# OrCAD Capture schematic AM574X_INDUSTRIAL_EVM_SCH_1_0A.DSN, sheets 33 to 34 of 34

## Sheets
33 Pg04: Processor Pwr Decoupling: size C
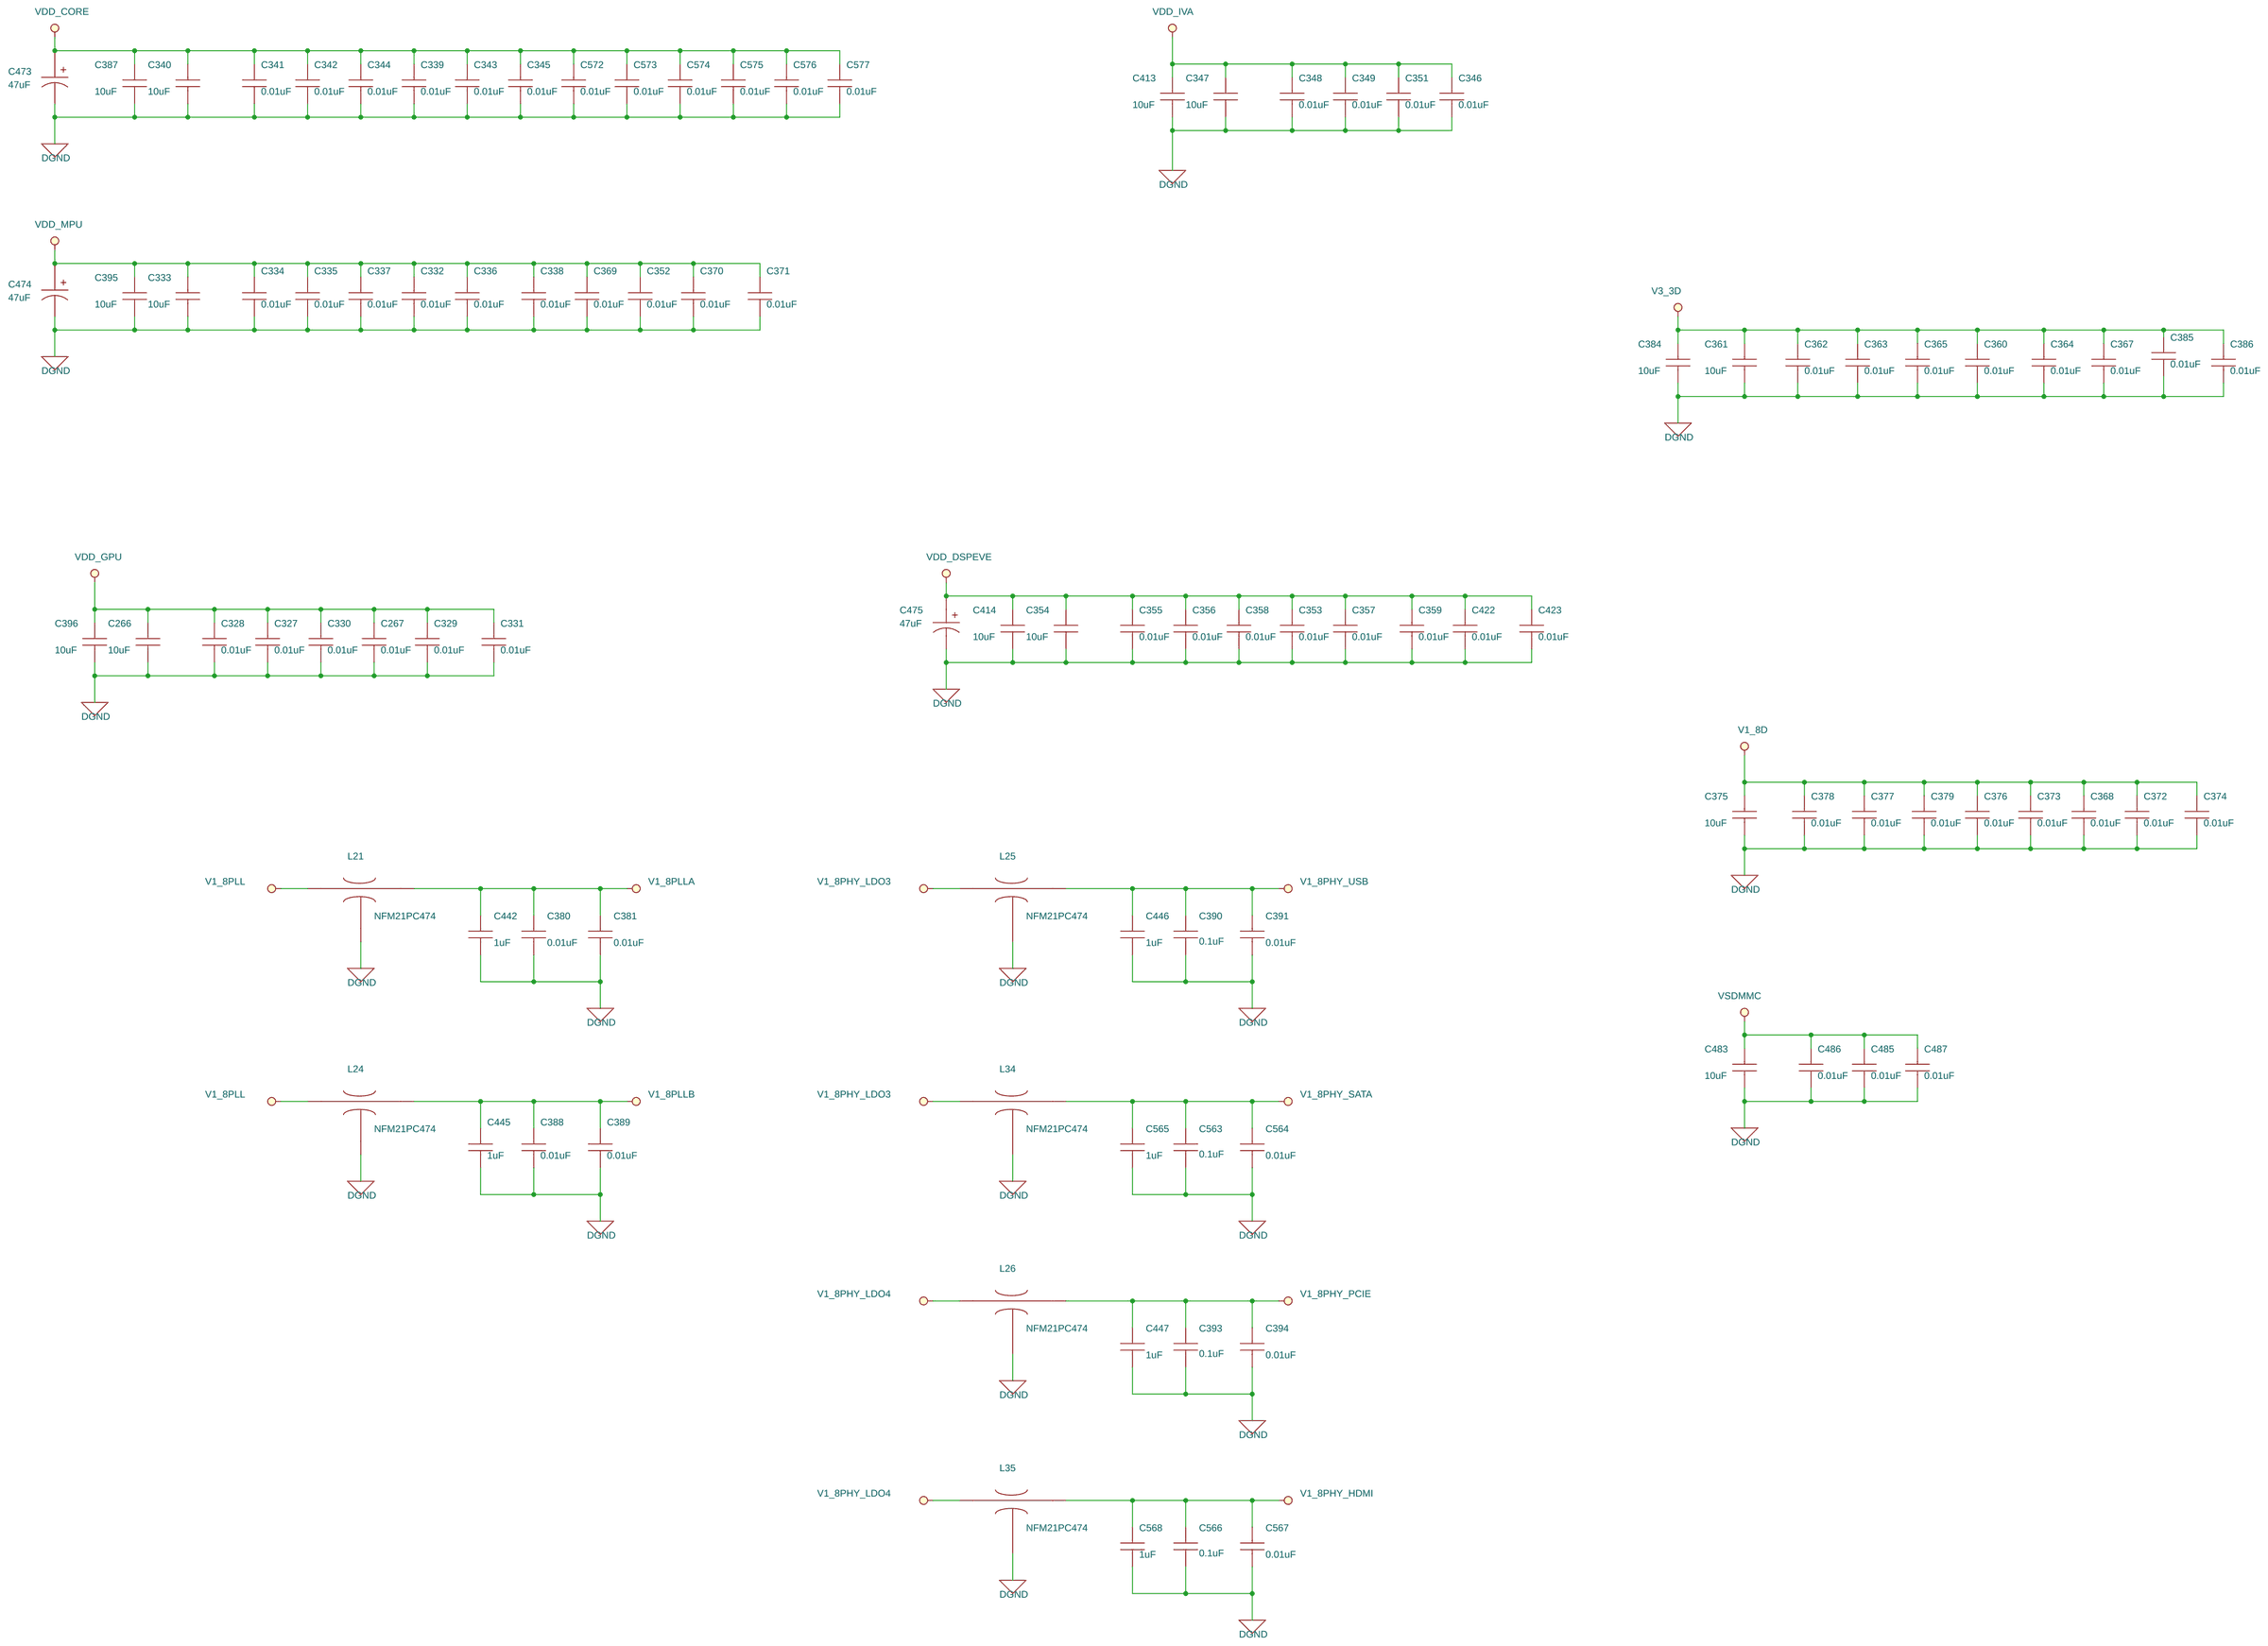
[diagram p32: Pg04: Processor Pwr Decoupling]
34 Pg15: Ind Ethrnt & Status LED's: size C
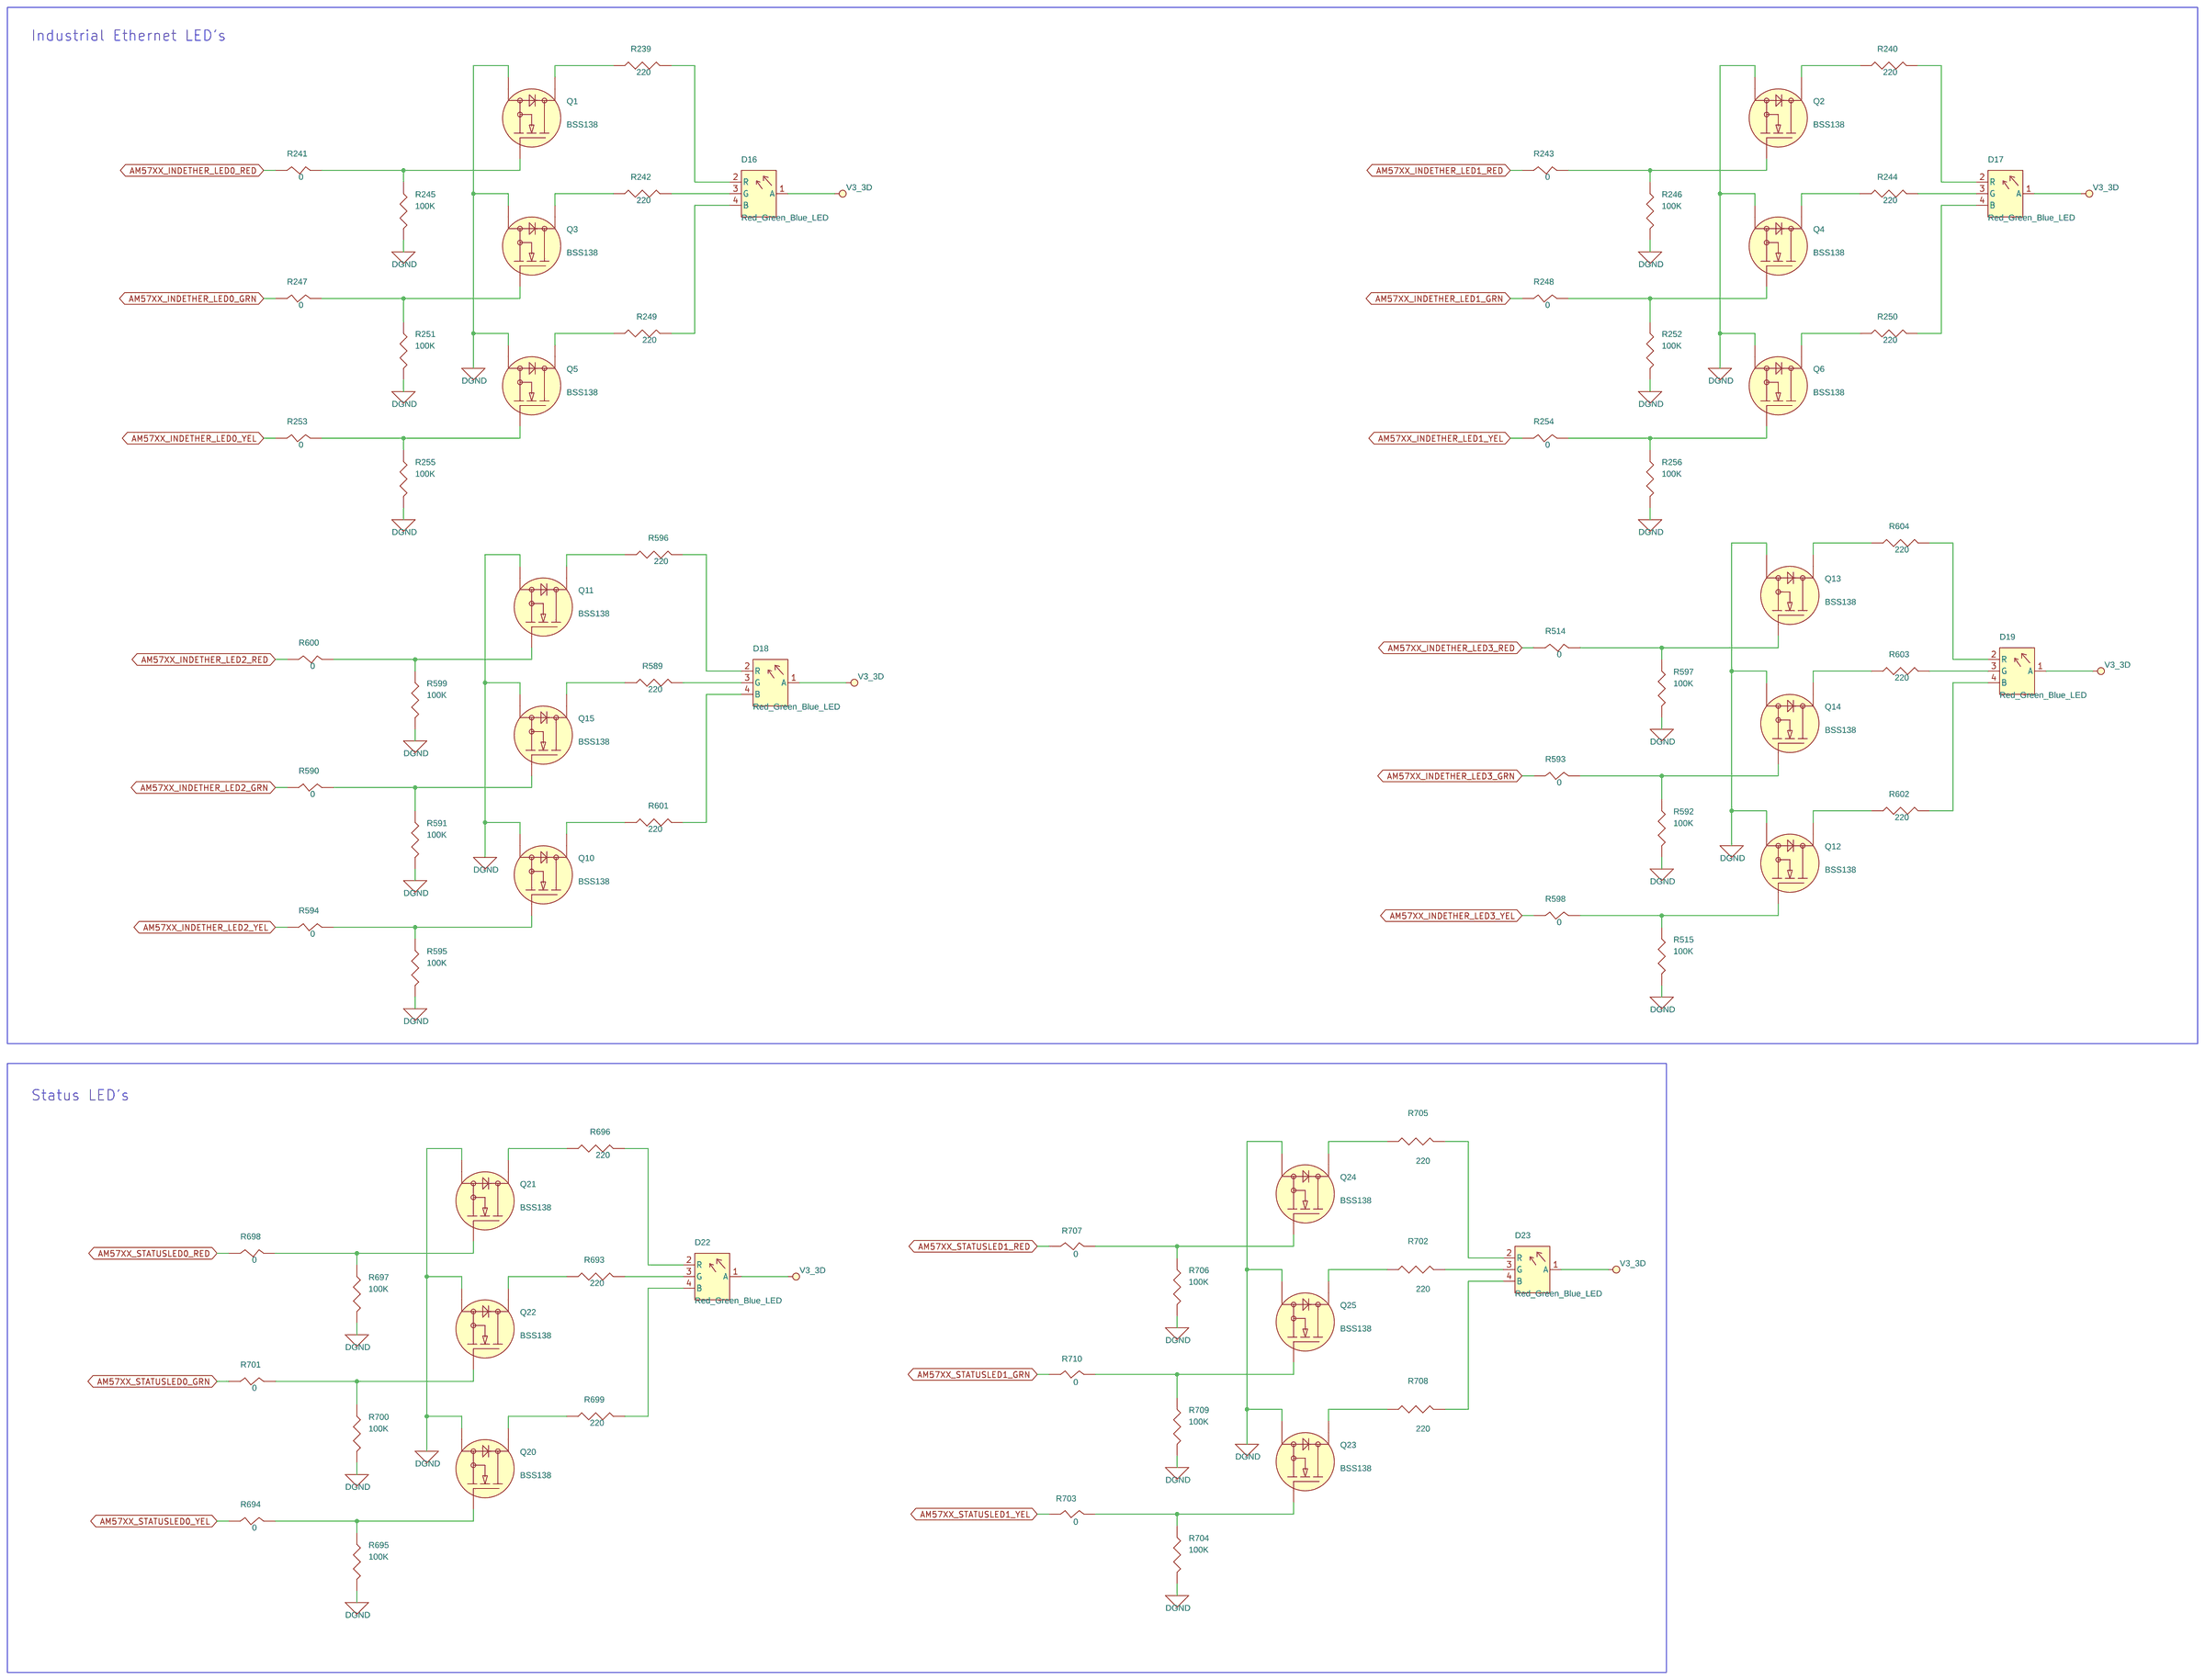
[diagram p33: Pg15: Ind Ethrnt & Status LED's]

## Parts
sheet Pg04: Processor Pwr Decoupling
C266  10uF  [SM-7351-CAP-0805]
C267  0.01uF  [SM-7351-CAP-0402]
C327  0.01uF  [SM-7351-CAP-0402]
C328  0.01uF  [SM-7351-CAP-0402]
C329  0.01uF  [SM-7351-CAP-0402]
C330  0.01uF  [SM-7351-CAP-0402]
C331  0.01uF  [SM-7351-CAP-0402]
C332  0.01uF  [SM-7351-CAP-0402]
C333  10uF  [SM-7351-CAP-0805]
C334  0.01uF  [SM-7351-CAP-0402]
C335  0.01uF  [SM-7351-CAP-0402]
C336  0.01uF  [SM-7351-CAP-0402]
C337  0.01uF  [SM-7351-CAP-0402]
C338  0.01uF  [SM-7351-CAP-0402]
C339  0.01uF  [SM-7351-CAP-0402]
C340  10uF  [SM-7351-CAP-0805]
C341  0.01uF  [SM-7351-CAP-0402]
C342  0.01uF  [SM-7351-CAP-0402]
C343  0.01uF  [SM-7351-CAP-0402]
C344  0.01uF  [SM-7351-CAP-0402]
C345  0.01uF  [SM-7351-CAP-0402]
C346  0.01uF  [SM-7351-CAP-0402]
C347  10uF  [SM-7351-CAP-0805]
C348  0.01uF  [SM-7351-CAP-0402]
C349  0.01uF  [SM-7351-CAP-0402]
C351  0.01uF  [SM-7351-CAP-0402]
C352  0.01uF  [SM-7351-CAP-0402]
C353  0.01uF  [SM-7351-CAP-0402]
C354  10uF  [SM-7351-CAP-0805]
C355  0.01uF  [SM-7351-CAP-0402]
C356  0.01uF  [SM-7351-CAP-0402]
C357  0.01uF  [SM-7351-CAP-0402]
C358  0.01uF  [SM-7351-CAP-0402]
C359  0.01uF  [SM-7351-CAP-0402]
C360  0.01uF  [SM-7351-CAP-0402]
C361  10uF  [SM-7351-CAP-0805]
C362  0.01uF  [SM-7351-CAP-0402]
C363  0.01uF  [SM-7351-CAP-0402]
C364  0.01uF  [SM-7351-CAP-0402]
C365  0.01uF  [SM-7351-CAP-0402]
C367  0.01uF  [SM-7351-CAP-0402]
C368  0.01uF  [SM-7351-CAP-0402]
C369  0.01uF  [SM-7351-CAP-0402]
C370  0.01uF  [SM-7351-CAP-0402]
C371  0.01uF  [SM-7351-CAP-0402]
C372  0.01uF  [SM-7351-CAP-0402]
C373  0.01uF  [SM-7351-CAP-0402]
C374  0.01uF  [SM-7351-CAP-0402]
C375  10uF  [SM-7351-CAP-0805]
C376  0.01uF  [SM-7351-CAP-0402]
C377  0.01uF  [SM-7351-CAP-0402]
C378  0.01uF  [SM-7351-CAP-0402]
C379  0.01uF  [SM-7351-CAP-0402]
C380  0.01uF  [SM-7351-CAP-0402]
C381  0.01uF  [SM-7351-CAP-0402]
C384  10uF  [SM-7351-CAP-0805]
C385  0.01uF  [SM-7351-CAP-0402]
C386  0.01uF  [SM-7351-CAP-0402]
C387  10uF  [SM-7351-CAP-0805]
C388  0.01uF  [SM-7351-CAP-0402]
C389  0.01uF  [SM-7351-CAP-0402]
C390  0.1uF  [SM-7351-CAP-0402]
C391  0.01uF  [SM-7351-CAP-0402]
C393  0.1uF  [SM-7351-CAP-0402]
C394  0.01uF  [SM-7351-CAP-0402]
C395  10uF  [SM-7351-CAP-0805]
C396  10uF  [SM-7351-CAP-0805]
C413  10uF  [SM-7351-CAP-0805]
C414  10uF  [SM-7351-CAP-0805]
C422  0.01uF  [SM-7351-CAP-0402]
C423  0.01uF  [SM-7351-CAP-0402]
C442  1uF  [SM-7351-CAP-0402]
C445  1uF  [SM-7351-CAP-0402]
C446  1uF  [SM-7351-CAP-0402]
C447  1uF  [SM-7351-CAP-0402]
C473  47uF  [7343]
C474  47uF  [7343]
C475  47uF  [7343]
C483  10uF  [SM-7351-CAP-0805]
C485  0.01uF  [SM-7351-CAP-0402]
C486  0.01uF  [SM-7351-CAP-0402]
C487  0.01uF  [SM-7351-CAP-0402]
C563  0.1uF  [SM-7351-CAP-0402]
C564  0.01uF  [SM-7351-CAP-0402]
C565  1uF  [SM-7351-CAP-0402]
C566  0.1uF  [SM-7351-CAP-0402]
C567  0.01uF  [SM-7351-CAP-0402]
C568  1uF  [SM-7351-CAP-0402]
C572  0.01uF  [SM-7351-CAP-0402]
C573  0.01uF  [SM-7351-CAP-0402]
C574  0.01uF  [SM-7351-CAP-0402]
C575  0.01uF  [SM-7351-CAP-0402]
C576  0.01uF  [SM-7351-CAP-0402]
C577  0.01uF  [SM-7351-CAP-0402]
L21  NFM21PC474  [FILT-NFM21PC]
L24  NFM21PC474  [FILT-NFM21PC]
L25  NFM21PC474  [FILT-NFM21PC]
L26  NFM21PC474  [FILT-NFM21PC]
L34  NFM21PC474  [FILT-NFM21PC]
L35  NFM21PC474  [FILT-NFM21PC]
sheet Pg15: Ind Ethrnt & Status LED's
D16  Red_Green_Blue_LED  [LED-SM1210]
D17  Red_Green_Blue_LED  [LED-SM1210]
D18  Red_Green_Blue_LED  [LED-SM1210]
D19  Red_Green_Blue_LED  [LED-SM1210]
D22  Red_Green_Blue_LED  [LED-SM1210]
D23  Red_Green_Blue_LED  [LED-SM1210]
Q1  BSS138  [SOT23-3]
Q2  BSS138  [SOT23-3]
Q3  BSS138  [SOT23-3]
Q4  BSS138  [SOT23-3]
Q5  BSS138  [SOT23-3]
Q6  BSS138  [SOT23-3]
Q10  BSS138  [SOT23-3]
Q11  BSS138  [SOT23-3]
Q12  BSS138  [SOT23-3]
Q13  BSS138  [SOT23-3]
Q14  BSS138  [SOT23-3]
Q15  BSS138  [SOT23-3]
Q20  BSS138  [SOT23-3]
Q21  BSS138  [SOT23-3]
Q22  BSS138  [SOT23-3]
Q23  BSS138  [SOT23-3]
Q24  BSS138  [SOT23-3]
Q25  BSS138  [SOT23-3]
R239  220  [SM-7351-RES-0402]
R240  220  [SM-7351-RES-0402]
R241  0  [SM-7351-RES-0402]
R242  220  [SM-7351-RES-0402]
R243  0  [SM-7351-RES-0402]
R244  220  [SM-7351-RES-0402]
R245  100K  [SM-7351-RES-0402]
R246  100K  [SM-7351-RES-0402]
R247  0  [SM-7351-RES-0402]
R248  0  [SM-7351-RES-0402]
R249  220  [SM-7351-RES-0402]
R250  220  [SM-7351-RES-0402]
R251  100K  [SM-7351-RES-0402]
R252  100K  [SM-7351-RES-0402]
R253  0  [SM-7351-RES-0402]
R254  0  [SM-7351-RES-0402]
R255  100K  [SM-7351-RES-0402]
R256  100K  [SM-7351-RES-0402]
R514  0  [SM-7351-RES-0402]
R515  100K  [SM-7351-RES-0402]
R589  220  [SM-7351-RES-0402]
R590  0  [SM-7351-RES-0402]
R591  100K  [SM-7351-RES-0402]
R592  100K  [SM-7351-RES-0402]
R593  0  [SM-7351-RES-0402]
R594  0  [SM-7351-RES-0402]
R595  100K  [SM-7351-RES-0402]
R596  220  [SM-7351-RES-0402]
R597  100K  [SM-7351-RES-0402]
R598  0  [SM-7351-RES-0402]
R599  100K  [SM-7351-RES-0402]
R600  0  [SM-7351-RES-0402]
R601  220  [SM-7351-RES-0402]
R602  220  [SM-7351-RES-0402]
R603  220  [SM-7351-RES-0402]
R604  220  [SM-7351-RES-0402]
R693  220  [SM-7351-RES-0402]
R694  0  [SM-7351-RES-0402]
R695  100K  [SM-7351-RES-0402]
R696  220  [SM-7351-RES-0402]
R697  100K  [SM-7351-RES-0402]
R698  0  [SM-7351-RES-0402]
R699  220  [SM-7351-RES-0402]
R700  100K  [SM-7351-RES-0402]
R701  0  [SM-7351-RES-0402]
R702  220  [SM-7351-RES-0402]
R703  0  [SM-7351-RES-0402]
R704  100K  [SM-7351-RES-0402]
R705  220  [SM-7351-RES-0402]
R706  100K  [SM-7351-RES-0402]
R707  0  [SM-7351-RES-0402]
R708  220  [SM-7351-RES-0402]
R709  100K  [SM-7351-RES-0402]
R710  0  [SM-7351-RES-0402]

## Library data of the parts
C266 C333 C340 C347 C354 C361 C375 C384 C387 C395 C396 C413 C414 C483 = 1C_10uFCapacitor16V10%0805
C267 C327-C332 C334-C339 C341-C346 C348 C349 C351-C353 C355-C360 C362-C365 C367-C374 C376-C381 C385 C386 C388 C389 C391 C394 C422 C423 C485-C487 C564 C567 C572-C577 = 1C_0.01uFCapacitor16V10%0402
C390 C393 C563 C566 = C0402C104J4RACTU: DescriptiveText: CAP, CER, 0.1 uF, 16V, 5%, X7R, 0402; Mfr: KEMET
C442 C445-C447 C565 C568 = GRT155R61E105KE01D: DescriptiveText: CAP, CER, 1 UF, 10%, 25V, X5R, 0402; Mfr: MURATA
C473-C475 = 1C_47uFCapacitor10V10%smd2917
L21 L24-L26 L34 L35 = 1L_NFM21PC474_EMIFilter_0
D16-D19 D22 D23 = SM1210RGB
Q1-Q6 Q10-Q15 Q20-Q25 = 1Q_MOSFET_NChan_BSS138_0
R239 R240 R242 R244 R249 R250 R589 R596 R601-R604 R693 R696 R699 R702 R705 R708 = 1R_150ohm1_16W1%SMD0402: DescriptiveText: Resistor 220ohm 1/10W 1% 0402; Mfr: Panasonic; MfrNum: ERJ-2RKF2200X; PartName: 220ohm1/10W1%0402; TIIntPartnumber: 1R0176
R241 R243 R247 R248 R253 R254 R514 R590 R593 R594 R598 R600 R694 R698 R701 R703 R707 R710 = 1R_ZeroOhmResistor1_16W0402
R245 R246 R251 R252 R255 R256 R515 R591 R592 R595 R597 R599 R695 R697 R700 R704 R706 R709 = 1R_100KOhmResistor1_16W0402

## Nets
DGND: C266.2 C267.2 C327.2 C328.2 C329.2 C330.2 C331.2 C332.2 C333.2 C334.2 C335.2 C336.2 C337.2 C338.2 C339.2 C340.2 C341.2 C342.2 C343.2 C344.2 C345.2 C346.2 C347.2 C348.2 C349.2 C351.2 C352.2 C353.2 C354.2 C355.2 C356.2 C357.2 C358.2 C359.2 C360.2 C361.2 C362.2 C363.2 C364.2 C365.2 C367.2 C368.2 C369.2 C370.2 C371.2 C372.2 C373.2 C374.2 C375.2 C376.2 C377.2 C378.2 C379.2 C380.2 C381.2 C384.2 C385.2 C386.2 C387.2 C388.2 C389.2 C390.2 C391.2 C393.2 C394.2 C395.2 C396.2 C413.2 C414.2 C422.2 C423.2 C442.2 C445.2 C446.2 C447.2 C473.2 C474.2 C475.2 C483.2 C485.2 C486.2 C487.2 C563.2 C564.2 C565.2 C566.2 C567.2 C568.2 C572.2 C573.2 C574.2 C575.2 C576.2 C577.2 L21.2(GND) L24.2(GND) L25.2(GND) L26.2(GND) L34.2(GND) L35.2(GND) Q1.S(SOURCE) Q2.S(SOURCE) Q3.S(SOURCE) Q4.S(SOURCE) Q5.S(SOURCE) Q6.S(SOURCE) Q10.S(SOURCE) Q11.S(SOURCE) Q12.S(SOURCE) Q13.S(SOURCE) Q14.S(SOURCE) Q15.S(SOURCE) Q20.S(SOURCE) Q21.S(SOURCE) Q22.S(SOURCE) Q23.S(SOURCE) Q24.S(SOURCE) Q25.S(SOURCE) R245.1(P1) R246.1(P1) R251.1(P1) R252.1(P1) R255.1(P1) R256.1(P1) R515.1(P1) R591.1(P1) R592.1(P1) R595.1(P1) R597.1(P1) R599.1(P1) R695.1(P1) R697.1(P1) R700.1(P1) R704.1(P1) R706.1(P1) R709.1(P1) ; also on sheet 1 2 3 4 5 6 8 9 10 11 12 14 15 16 17 18 19 20 21 22 23 24 25 26 27 28 29 30 31 32
V1_8D: C368.1 C372.1 C373.1 C374.1 C375.1 C376.1 C377.1 C378.1 C379.1 ; also on sheet 5 20 23 26 28 30
V1_8PHY_HDMI: C566.1 C567.1 C568.1 L35.3(OUT) ; also on sheet 23
V1_8PHY_LDO3: L25.1(IN) L34.1(IN) ; also on sheet 20
V1_8PHY_LDO4: L26.1(IN) L35.1(IN) ; also on sheet 20
V1_8PHY_PCIE: C393.1 C394.1 C447.1 L26.3(OUT) ; also on sheet 23
V1_8PHY_SATA: C563.1 C564.1 C565.1 L34.3(OUT) ; also on sheet 23
V1_8PHY_USB: C390.1 C391.1 C446.1 L25.3(OUT) ; also on sheet 23
V1_8PLL: L21.1(IN) L24.1(IN) ; also on sheet 20 23
V1_8PLLA: C380.1 C381.1 C442.1 L21.3(OUT) ; also on sheet 23
V1_8PLLB: C388.1 C389.1 C445.1 L24.3(OUT) ; also on sheet 23
V3_3D: C360.1 C361.1 C362.1 C363.1 C364.1 C365.1 C367.1 C384.1 C385.1 C386.1 D16.1(A) D17.1(A) D18.1(A) D19.1(A) D22.1(A) D23.1(A) ; also on sheet 2 3 4 5 6 8 9 10 11 12 14 15 17 18 19 20 21 22 23 24 25 26 27 28 29 30 31 32
VDD_CORE: C339.1 C340.1 C341.1 C342.1 C343.1 C344.1 C345.1 C387.1 C473.1 C572.1 C573.1 C574.1 C575.1 C576.1 C577.1 ; also on sheet 19 23
VDD_DSPEVE: C353.1 C354.1 C355.1 C356.1 C357.1 C358.1 C359.1 C414.1 C422.1 C423.1 C475.1 ; also on sheet 19 23
VDD_GPU: C266.1 C267.1 C327.1 C328.1 C329.1 C330.1 C331.1 C396.1 ; also on sheet 19 23
VDD_IVA: C346.1 C347.1 C348.1 C349.1 C351.1 C413.1 ; also on sheet 19 23
VDD_MPU: C332.1 C333.1 C334.1 C335.1 C336.1 C337.1 C338.1 C352.1 C369.1 C370.1 C371.1 C395.1 C474.1 ; also on sheet 19 23
AM57XX_INDETHER_LED0_GRN: R247.1(P1) ; also on sheet 31
AM57XX_INDETHER_LED0_RED: R241.2(P2) ; also on sheet 31
AM57XX_INDETHER_LED0_YEL: R253.1(P1) ; also on sheet 31
AM57XX_INDETHER_LED1_GRN: R248.1(P1) ; also on sheet 31
AM57XX_INDETHER_LED1_RED: R243.2(P2) ; also on sheet 31
AM57XX_INDETHER_LED1_YEL: R254.1(P1) ; also on sheet 31
AM57XX_INDETHER_LED2_GRN: R590.1(P1) ; also on sheet 31
AM57XX_INDETHER_LED2_RED: R600.2(P2) ; also on sheet 31
AM57XX_INDETHER_LED2_YEL: R594.1(P1) ; also on sheet 31
AM57XX_INDETHER_LED3_GRN: R593.1(P1) ; also on sheet 31
AM57XX_INDETHER_LED3_RED: R514.2(P2) ; also on sheet 31
AM57XX_INDETHER_LED3_YEL: R598.1(P1) ; also on sheet 31
AM57XX_STATUSLED0_GRN: R701.1(P1) ; also on sheet 31
AM57XX_STATUSLED0_RED: R698.2(P2) ; also on sheet 31
AM57XX_STATUSLED0_YEL: R694.1(P1) ; also on sheet 31
AM57XX_STATUSLED1_GRN: R710.1(P1) ; also on sheet 31
AM57XX_STATUSLED1_RED: R707.2(P2) ; also on sheet 31
AM57XX_STATUSLED1_YEL: R703.1(P1) ; also on sheet 31
VSDMMC: C483.1 C485.1 C486.1 C487.1 ; also on sheet 20 23 29
N17731118: Q1.G(GATE) R241.1(P1) R245.2(P2)
N17731139: Q5.G(GATE) R253.2(P2) R255.2(P2)
N20721609: Q3.G(GATE) R247.2(P2) R251.2(P2)
N20721766: Q3.D(DRAIN) R242.1(P1)
N20721850: Q1.D(DRAIN) R239.1(P1)
N20722196: D16.3(G) R242.2(P2)
N20722199: Q5.D(DRAIN) R249.1(P1)
N20722204: D16.4(B) R249.2(P2)
N20722213: D16.2(R) R239.2(P2)
N20722605: Q2.G(GATE) R243.1(P1) R246.2(P2)
N20722618: Q6.G(GATE) R254.2(P2) R256.2(P2)
N20722739: Q4.G(GATE) R248.2(P2) R252.2(P2)
N20722773: Q4.D(DRAIN) R244.1(P1)
N20722790: Q2.D(DRAIN) R240.1(P1)
N20722809: D17.3(G) R244.2(P2)
N20722811: Q6.D(DRAIN) R250.1(P1)
N20722815: D17.4(B) R250.2(P2)
N20722821: D17.2(R) R240.2(P2)
N20723137: Q11.G(GATE) R599.2(P2) R600.1(P1)
N20723150: Q10.G(GATE) R594.2(P2) R595.2(P2)
N20723271: Q15.G(GATE) R590.2(P2) R591.2(P2)
N20723305: Q15.D(DRAIN) R589.1(P1)
N20723322: Q11.D(DRAIN) R596.1(P1)
N20723341: D18.3(G) R589.2(P2)
N20723343: Q10.D(DRAIN) R601.1(P1)
N20723347: D18.4(B) R601.2(P2)
N20723353: D18.2(R) R596.2(P2)
N20723697: Q13.G(GATE) R514.1(P1) R597.2(P2)
N20723710: Q12.G(GATE) R515.2(P2) R598.2(P2)
N20723831: Q14.G(GATE) R592.2(P2) R593.2(P2)
N20723865: Q14.D(DRAIN) R603.1(P1)
N20723882: Q13.D(DRAIN) R604.1(P1)
N20723901: D19.3(G) R603.2(P2)
N20723903: Q12.D(DRAIN) R602.1(P1)
N20723907: D19.4(B) R602.2(P2)
N20723913: D19.2(R) R604.2(P2)
N20729664: Q20.D(DRAIN) R699.1(P1)
N20729666: D22.4(B) R699.2(P2)
N20729672: D22.2(R) R696.2(P2)
N20729903: Q21.G(GATE) R697.2(P2) R698.1(P1)
N20729915: Q20.G(GATE) R694.2(P2) R695.2(P2)
N20730029: Q22.G(GATE) R700.2(P2) R701.2(P2)
N20730054: Q22.D(DRAIN) R693.1(P1)
N20730079: Q21.D(DRAIN) R696.1(P1)
N20730095: D22.3(G) R693.2(P2)
N20730773: Q23.D(DRAIN) R708.1(P1)
N20730775: D23.4(B) R708.2(P2)
N20730781: D23.2(R) R705.2(P2)
N20730789: Q24.G(GATE) R706.2(P2) R707.1(P1)
N20730805: Q23.G(GATE) R703.2(P2) R704.2(P2)
N20730910: Q25.G(GATE) R709.2(P2) R710.2(P2)
N20730936: Q25.D(DRAIN) R702.1(P1)
N20730961: Q24.D(DRAIN) R705.1(P1)
N20730985: D23.3(G) R702.2(P2)

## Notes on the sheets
sheet 34
- Industrial Ethernet LED's
- Status LED's
